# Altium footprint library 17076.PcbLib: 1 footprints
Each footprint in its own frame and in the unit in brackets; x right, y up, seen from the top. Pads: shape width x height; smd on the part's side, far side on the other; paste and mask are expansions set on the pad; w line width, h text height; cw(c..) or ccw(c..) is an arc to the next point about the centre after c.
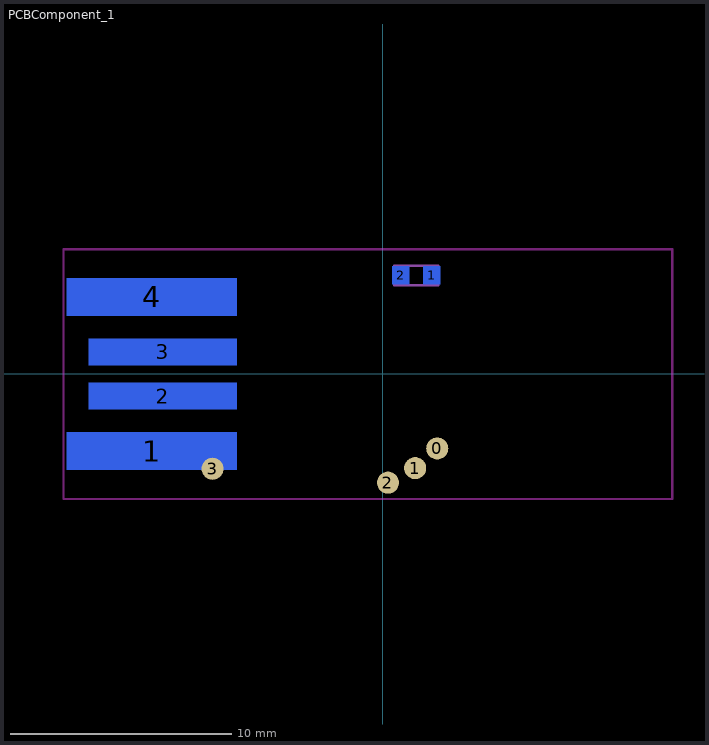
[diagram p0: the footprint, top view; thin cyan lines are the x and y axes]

## PCBComponent_1 [mm]
pads (10):
  round 1 smd: 0(2.46,-3.386) 1(1.46,-4.276) 2(0.23,-4.936) 3(-7.71,-4.306)
  rect 7.7x1.7 smd far side: 1(-10.46,-3.506) 4(-10.46,3.474)
  rect 0.762x0.813 smd far side: 1(2.209,4.444) 2(0.812,4.444)
  rect 6.7x1.2 smd far side: 2(-9.96,-1.016) 3(-9.96,0.984)
Bottom Overlay:
  region: -13.35,-2.076 -13.35,1.674 -14.32,1.674 -14.32,-2.076
  rectangle: -14.32,-2.616 -6.5,-1.646
  rectangle: -14.32,1.634 -6.48,2.604
  rectangle: -13.37,-0.366 -6.5,0.344
  lines w0.127: 1.193,3.936 0.304,3.936 0.304,4.952 1.193,4.952 ; 1.828,3.936 2.717,3.936 ; 1.828,4.952 2.717,4.952 ; 2.717,3.936 2.971,4.19 2.971,4.698 2.717,4.952 ; 2.717,3.936 2.717,4.952
  lines w0.152: -14.457,-4.536 -14.457,4.504 -6.43,4.504 -6.43,-4.536 -14.457,-4.536
  text "YJ-17076-USB-UART" at 6.01,-3.826 h0.55
Keep-Out Layer:
  lines w0.1: -14.457,-5.668 -14.457,5.632 13.093,5.632 13.093,-5.668 -14.457,-5.668
Mechanical 7:
  lines w0.1: 0.81,4.005 0.81,4.883 ; 0.91,4.005 0.91,4.883 ; 2.11,4.005 2.11,4.883 ; 2.21,4.005 2.21,4.883 ; 0.51,4.005 0.51,4.883 2.51,4.883 2.51,4.005 0.51,4.005
  text "LED_G" at 2.01,4.319 h0.3
3D body: height 0.6, standoff 0, extent 0.694,4.044 2.314,4.844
